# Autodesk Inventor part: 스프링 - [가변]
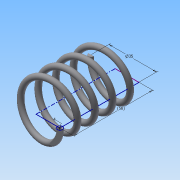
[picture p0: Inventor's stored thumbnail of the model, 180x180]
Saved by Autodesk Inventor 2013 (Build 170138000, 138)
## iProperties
Created: 2015-03
Part Number: 스프링 - [가변]
Material: 강철, 탄소
Document SubType Name: Modeling
Designer: Administrator
Density: 7.87 g/cm^3
Mass: 47.9935 g
Surface Area: 62.0176 cm^2
Volume: 6.09829 cm^3
Author: Administrator
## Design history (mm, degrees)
sketch "스케치1"
  geometry: L1 (0, 0)-(17.5, 0); L2 (17.5, 0)-(17.5, 43.5); L3 (17.5, 43.5)-(0, 43.5); L4 (0, 43.5)-(0, 0); C1 r 2 at (17.5, 0)
  constraints: 8 end point, 2 parallel, 1 centre point, 1 coincident, 1 horizontal, 1 perpendicular
  dimensions: "d0" = 35 diameter of L2 L4; "d2" = 43.5 distance of L1.end L2.end (derived); "d3" = 4 diameter of C1
feature "코일1" pitch "d4" = 10; turns "d6" = 4.5; dims "d5" = 43.5 (= d2), "d7" = 0, angle "d8" = 90 deg, angle "d9" = 90 deg, "d10" = 0, "d11" = 0
node "작업 평면1"
sketch "스케치2"
  geometry: L1 (-19.5, 0)-(-15.5, 0) reference; 1 further point
  constraints: 1 horizontal alignment
extrude "돌출1" cut sketch "스케치2" stored distance "d13" = 10; taper "d14" = 0 deg
node "작업 평면2"
sketch "스케치3"
  geometry: L1 (15.5, 0)-(19.5, 0) reference; 1 further point
  constraints: 1 horizontal alignment
extrude "돌출2" cut sketch "스케치3" stored distance "d16" = 10; taper "d17" = 0 deg
node "솔리드1"
node "절단 모서리 투영1"
node "절단 모서리 투영2"
other parameters: "d12" = 0, "d15" = 43.5 (= d2)
